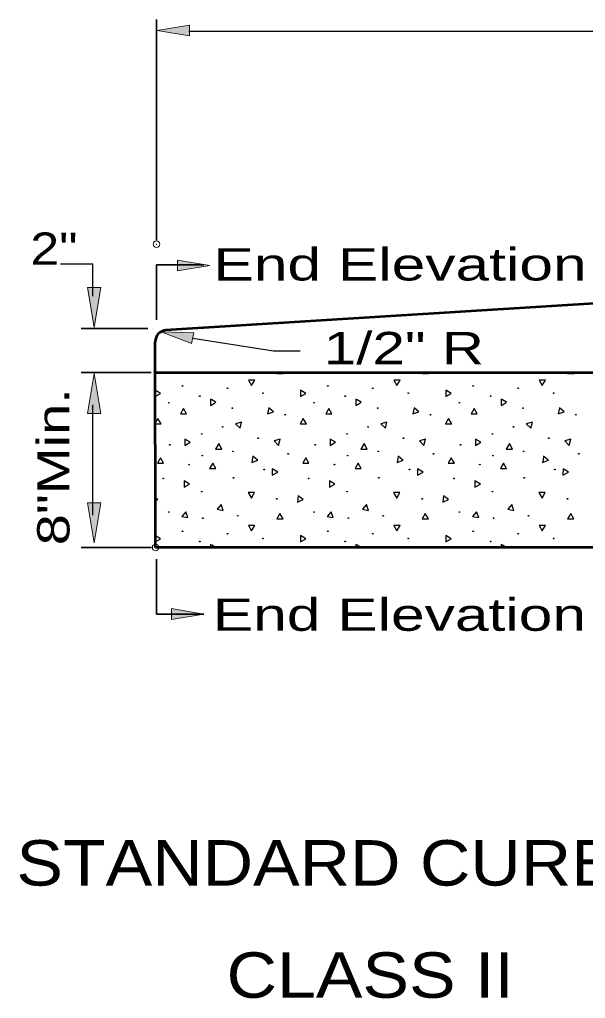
# Model space of a CAD drawing. Extents: x 75.6 to 110.9, y 28 to 50.
# Drawn here: x 82.636 to 85.264, y 34.838 to 39.383 of the extents above; entities that cross this region are included whole.
import ezdxf

# ---------------------------------------------------------------- set-up
doc = ezdxf.new("R2010")
doc.units = 0
doc.header["$LTSCALE"] = 0.06
doc.header["$PDMODE"] = 32
doc.header["$PDSIZE"] = 0.03
doc.layers.add('1', color=7, linetype='Continuous', lineweight=25)
doc.layers.add('3', color=7, linetype='Continuous', lineweight=13)

msp = doc.modelspace()

# ---------------------------------------------------------------- hatches: boundary and pattern name
at = {"layer": '3'}
for points in [[(83.42558, 39.3575), (83.42558, 39.3075), (83.27558, 39.3325), (83.27558, 39.3325)], [(83.36975, 38.216), (83.36975, 38.266), (83.51975, 38.241), (83.51975, 38.241)], [(82.9525, 38.1395), (83.014, 38.1395), (82.98317, 37.95492), (82.98317, 37.95492)], [(83.43533, 37.879), (83.44533, 37.928), (83.29333, 37.93342), (83.29333, 37.93342)], [(82.9525, 37.55467), (83.014, 37.55467), (82.98317, 37.73925), (82.98317, 37.73925)], [(82.9525, 37.1385), (83.014, 37.1385), (82.98317, 36.95392), (82.98317, 36.95392)], [(83.34183, 36.59792), (83.34183, 36.64792), (83.49183, 36.62292), (83.49183, 36.62292)]]:
    msp.add_hatch(color=256, dxfattribs=at).paths.add_polyline_path(points)

# ---------------------------------------------------------------- linework, layer by layer
at = {"layer": '1', "lineweight": 53}
for p, q in [((89.3085, 38.31592), (83.31608, 37.94033)), ((83.26817, 36.932), (83.26617, 37.8865)), ((83.26617, 37.74358), (90.5905, 37.74358)), ((90.61742, 36.932), (83.26817, 36.932))]:
    msp.add_line(p, q, dxfattribs=at)
at = {"layer": '1'}
for p, q in [((83.83375, 37.74358), (83.83117, 37.73917)), ((84.50875, 37.74358), (84.50617, 37.73917)), ((85.18375, 37.74358), (85.18117, 37.73917)), ((83.52325, 37.6205), (83.52317, 37.59142)), ((83.52317, 37.59142), (83.52908, 37.59475)), ((83.52908, 37.61717), (83.52325, 37.6205)), ((83.52908, 37.61717), (83.52325, 37.6205)), ((84.19825, 37.6205), (84.19817, 37.59142)), ((84.19817, 37.59142), (84.20408, 37.59475)), ((84.20408, 37.61717), (84.19825, 37.6205)), ((84.20408, 37.61717), (84.19825, 37.6205)), ((84.87325, 37.6205), (84.87317, 37.59142)), ((84.87317, 37.59142), (84.87908, 37.59475)), ((84.87908, 37.61717), (84.87325, 37.6205)), ((84.87908, 37.61717), (84.87325, 37.6205)), ((83.28475, 37.338), (83.27625, 37.32358)), ((83.27625, 37.32358), (83.3055, 37.32358)), ((83.3055, 37.32358), (83.29708, 37.338)), ((83.52908, 37.316), (83.51917, 37.29892)), ((83.53375, 37.32408), (83.52908, 37.316)), ((83.54825, 37.29892), (83.53375, 37.32408)), ((83.71725, 37.338), (83.71525, 37.32658)), ((83.71525, 37.32658), (83.7425, 37.33667)), ((83.7425, 37.33667), (83.74083, 37.338)), ((83.95975, 37.338), (83.95125, 37.32358)), ((83.95125, 37.32358), (83.9805, 37.32358)), ((83.9805, 37.32358), (83.97208, 37.338)), ((84.20408, 37.316), (84.19417, 37.29892)), ((84.20875, 37.32408), (84.20408, 37.316)), ((84.22325, 37.29892), (84.20875, 37.32408)), ((84.39225, 37.338), (84.39025, 37.32658)), ((84.39025, 37.32658), (84.4175, 37.33667)), ((84.4175, 37.33667), (84.41583, 37.338)), ((84.63475, 37.338), (84.62625, 37.32358)), ((84.62625, 37.32358), (84.6555, 37.32358)), ((84.6555, 37.32358), (84.64708, 37.338)), ((84.87908, 37.316), (84.86917, 37.29892)), ((84.88375, 37.32408), (84.87908, 37.316)), ((84.89825, 37.29892), (84.88375, 37.32408)), ((85.06725, 37.338), (85.06525, 37.32658)), ((85.06525, 37.32658), (85.0925, 37.33667)), ((85.0925, 37.33667), (85.09083, 37.338)), ((83.51917, 37.29892), (83.52908, 37.29892)), ((83.52908, 37.29892), (83.54825, 37.29892)), ((84.19417, 37.29892), (84.20408, 37.29892)), ((84.20408, 37.29892), (84.22325, 37.29892)), ((84.86917, 37.29892), (84.87908, 37.29892)), ((84.87908, 37.29892), (84.89825, 37.29892)), ((83.52325, 36.9455), (83.52325, 36.932)), ((83.52325, 36.9455), (83.52325, 36.932)), ((83.52908, 36.94217), (83.52325, 36.9455)), ((83.52908, 36.94217), (83.52325, 36.9455)), ((83.54658, 36.932), (83.52908, 36.94217)), ((84.19825, 36.9455), (84.19825, 36.932)), ((84.19825, 36.9455), (84.19825, 36.932)), ((84.20408, 36.94217), (84.19825, 36.9455)), ((84.20408, 36.94217), (84.19825, 36.9455)), ((84.22158, 36.932), (84.20408, 36.94217)), ((84.87325, 36.9455), (84.87325, 36.932)), ((84.87325, 36.9455), (84.87325, 36.932)), ((84.87908, 36.94217), (84.87325, 36.9455)), ((84.87908, 36.94217), (84.87325, 36.9455)), ((84.89658, 36.932), (84.87908, 36.94217))]:
    msp.add_line(p, q, dxfattribs=at)
for points in [[(83.83117, 37.73917), (83.86025, 37.73917), (83.85767, 37.74358)], [(84.50617, 37.73917), (84.53525, 37.73917), (84.53267, 37.74358)], [(85.18117, 37.73917), (85.21025, 37.73917), (85.20767, 37.74358)], [(83.26617, 37.63283), (83.29133, 37.64733), (83.26625, 37.66192), (83.26617, 37.64733)], [(83.52325, 37.6205), (83.52317, 37.59142), (83.52908, 37.59475)], [(83.52908, 37.59475), (83.54842, 37.60592), (83.52908, 37.61717)], [(84.19825, 37.6205), (84.19817, 37.59142), (84.20408, 37.59475)], [(84.20408, 37.59475), (84.22342, 37.60592), (84.20408, 37.61717)], [(84.87325, 37.6205), (84.87317, 37.59142), (84.87908, 37.59475)], [(84.87908, 37.59475), (84.89842, 37.60592), (84.87908, 37.61717)], [(83.26617, 37.50533), (83.29325, 37.50533), (83.27875, 37.5305), (83.26617, 37.50875)], [(83.29708, 37.338), (83.29092, 37.34867), (83.28475, 37.338)], [(83.74083, 37.338), (83.72033, 37.35517), (83.71725, 37.338)], [(83.74083, 37.338), (83.72033, 37.35517), (83.71725, 37.338)], [(83.97208, 37.338), (83.96592, 37.34867), (83.95975, 37.338)], [(84.41583, 37.338), (84.39533, 37.35517), (84.39225, 37.338)], [(84.41583, 37.338), (84.39533, 37.35517), (84.39225, 37.338)], [(84.64708, 37.338), (84.64092, 37.34867), (84.63475, 37.338)], [(85.09083, 37.338), (85.07033, 37.35517), (85.06725, 37.338)], [(85.09083, 37.338), (85.07033, 37.35517), (85.06725, 37.338)], [(83.26617, 37.14892), (83.27833, 37.15458), (83.26617, 37.16308)], [(83.26617, 36.95783), (83.29133, 36.97233), (83.26625, 36.98692), (83.26617, 36.97233)]]:
    msp.add_lwpolyline(points, dxfattribs=at)
for points in [[(83.71383, 37.68408), (83.7285, 37.70933), (83.69933, 37.70933)], [(84.38883, 37.68408), (84.4035, 37.70933), (84.37433, 37.70933)], [(85.06383, 37.68408), (85.0785, 37.70933), (85.04933, 37.70933)], [(83.94108, 37.63275), (83.96633, 37.64733), (83.94125, 37.66192)], [(84.61608, 37.63275), (84.64133, 37.64733), (84.61625, 37.66192)], [(83.383, 37.55258), (83.41208, 37.55258), (83.39758, 37.57767)], [(83.78825, 37.55192), (83.81558, 37.56192), (83.79333, 37.5805)], [(84.058, 37.55258), (84.08708, 37.55258), (84.07258, 37.57767)], [(84.46325, 37.55192), (84.49058, 37.56192), (84.46833, 37.5805)], [(84.733, 37.55258), (84.76208, 37.55258), (84.74758, 37.57767)], [(85.13825, 37.55192), (85.16558, 37.56192), (85.14333, 37.5805)], [(83.66025, 37.48592), (83.66775, 37.51417), (83.63975, 37.50658)], [(83.93917, 37.50533), (83.96825, 37.50533), (83.95375, 37.5305)], [(84.33525, 37.48592), (84.34275, 37.51417), (84.31475, 37.50658)], [(84.61417, 37.50533), (84.64325, 37.50533), (84.62875, 37.5305)], [(85.01025, 37.48592), (85.01775, 37.51417), (84.98975, 37.50658)], [(83.40367, 37.40592), (83.42892, 37.4205), (83.40383, 37.43508)], [(83.54675, 37.38892), (83.57592, 37.38892), (83.56142, 37.41417)], [(83.83867, 37.40592), (83.84617, 37.43408), (83.81808, 37.42658)], [(84.07867, 37.40592), (84.10392, 37.4205), (84.07883, 37.43508)], [(84.22175, 37.38892), (84.25092, 37.38892), (84.23642, 37.41417)], [(84.51367, 37.40592), (84.52117, 37.43408), (84.49308, 37.42658)], [(84.75367, 37.40592), (84.77892, 37.4205), (84.75383, 37.43508)], [(84.89675, 37.38892), (84.92592, 37.38892), (84.91142, 37.41417)], [(85.18867, 37.40592), (85.19617, 37.43408), (85.16808, 37.42658)], [(83.81, 37.2675), (83.83525, 37.28208), (83.81017, 37.29667)], [(84.485, 37.2675), (84.51025, 37.28208), (84.48517, 37.29667)], [(85.16, 37.2675), (85.18525, 37.28208), (85.16017, 37.29667)], [(83.401, 37.21175), (83.42625, 37.22642), (83.40117, 37.24092)], [(84.076, 37.21175), (84.10125, 37.22642), (84.07617, 37.24092)], [(84.751, 37.21175), (84.77625, 37.22642), (84.75117, 37.24092)], [(83.71275, 37.16117), (83.72733, 37.18642), (83.69825, 37.18642)], [(84.38775, 37.16117), (84.40233, 37.18642), (84.37325, 37.18642)], [(85.06275, 37.16117), (85.07733, 37.18642), (85.04825, 37.18642)], [(83.55333, 37.10925), (83.582, 37.10417), (83.57208, 37.1315)], [(83.92692, 37.14233), (83.95333, 37.15458), (83.9295, 37.17125)], [(84.22833, 37.10925), (84.257, 37.10417), (84.24708, 37.1315)], [(84.60192, 37.14233), (84.62833, 37.15458), (84.6045, 37.17125)], [(84.90333, 37.10925), (84.932, 37.10417), (84.92208, 37.1315)], [(83.38983, 37.07575), (83.4185, 37.07067), (83.4085, 37.09808)], [(83.83117, 37.06417), (83.86025, 37.06417), (83.84575, 37.08925)], [(84.06483, 37.07575), (84.0935, 37.07067), (84.0835, 37.09808)], [(84.50617, 37.06417), (84.53525, 37.06417), (84.52075, 37.08925)], [(84.73983, 37.07575), (84.7685, 37.07067), (84.7585, 37.09808)], [(85.18117, 37.06417), (85.21025, 37.06417), (85.19575, 37.08925)], [(83.71383, 37.00908), (83.7285, 37.03433), (83.69933, 37.03433)], [(84.38883, 37.00908), (84.4035, 37.03433), (84.37433, 37.03433)], [(85.06383, 37.00908), (85.0785, 37.03433), (85.04933, 37.03433)], [(83.94108, 36.95775), (83.96633, 36.97233), (83.94125, 36.98692)], [(84.61608, 36.95775), (84.64133, 36.97233), (84.61625, 36.98692)]]:
    msp.add_lwpolyline(points, close=True, dxfattribs=at)
for centre in [(83.39296, 37.68203), (84.06796, 37.68203), (84.74296, 37.68203), (83.47385, 37.63461), (83.60221, 37.67089), (83.76674, 37.64856), (84.14885, 37.63461), (84.27721, 37.67089), (84.44174, 37.64856), (84.82385, 37.63461), (84.95221, 37.67089), (85.11674, 37.64856), (83.32883, 37.60395), (84.00383, 37.60395), (84.67883, 37.60395), (83.62448, 37.57886), (83.86996, 37.54815), (84.29948, 37.57886), (84.54496, 37.54815), (84.97448, 37.57886), (85.21996, 37.54815), (83.57988, 37.49241), (84.25488, 37.49241), (84.92988, 37.49241), (83.48223, 37.45894), (84.15723, 37.45894), (84.83223, 37.45894), (83.3344, 37.40871), (83.74441, 37.43936), (84.0094, 37.40871), (84.41941, 37.43936), (84.6844, 37.40871), (85.09441, 37.43936), (83.48498, 37.35853), (83.6273, 37.37805), (83.88391, 37.36686), (84.15998, 37.35853), (84.3023, 37.37805), (84.55891, 37.36686), (84.83498, 37.35853), (84.9773, 37.37805), (85.23391, 37.36686), (83.42361, 37.31663), (84.09861, 37.31663), (84.77361, 37.31663), (83.77231, 37.29429), (84.44731, 37.29429), (85.12231, 37.29429), (83.30369, 37.2525), (83.63005, 37.25526), (83.97869, 37.2525), (84.30505, 37.25526), (84.65369, 37.2525), (84.98005, 37.25526), (83.48223, 37.19113), (84.15723, 37.19113), (84.83223, 37.19113), (83.83086, 37.15766), (84.50586, 37.15766), (85.18086, 37.15766), (83.32883, 37.09629), (84.00383, 37.09629), (84.67883, 37.09629), (83.4878, 37.06839), (83.64963, 37.07953), (84.1628, 37.06839), (84.32463, 37.07953), (84.8378, 37.06839), (84.99963, 37.07953), (83.39296, 37.00703), (83.60221, 36.99589), (84.06796, 37.00703), (84.27721, 36.99589), (84.74296, 37.00703), (84.95221, 36.99589), (83.47385, 36.95961), (83.76674, 36.97356), (84.14885, 36.95961), (84.44174, 36.97356), (84.82385, 36.95961), (85.11674, 36.97356)]:
    msp.add_circle(centre, 0.00162, dxfattribs=at)
at = {"layer": '1', "lineweight": 53}
msp.add_arc((83.32015, 37.88648), 0.054, 94.37495, 180, dxfattribs=at)
at = {"layer": '1'}
for centre in [(83.4878, 37.74339), (84.1628, 37.74339), (84.8378, 37.74339)]:
    msp.add_arc(centre, 0.00162, 173.26839, 6.73161, dxfattribs=at)
at = {"layer": '3', "lineweight": 35}
for p, q in [((83.27208, 38.35858), (83.27208, 39.38283)), ((83.23267, 37.94833), (82.92275, 37.94833)), ((83.24767, 37.74358), (82.92275, 37.74358)), ((83.24942, 36.932), (82.92275, 36.932)), ((83.27208, 36.877), (83.27208, 36.62292)), ((83.27208, 36.62292), (83.49183, 36.62292))]:
    msp.add_line(p, q, dxfattribs=at)
at = {"layer": '3', "lineweight": 25}
for p, q in [((83.42208, 39.32883), (89.60558, 39.32883)), ((82.82675, 38.24833), (82.97675, 38.24833)), ((82.97675, 38.09833), (82.97675, 38.24833)), ((82.97675, 37.082), (82.97675, 37.59358))]:
    msp.add_line(p, q, dxfattribs=at)
at = {"layer": '3'}
for p, q in [((82.97675, 37.94833), (82.97683, 37.94833)), ((83.25142, 37.94833), (83.2515, 37.94833)), ((83.24767, 37.74358), (82.92275, 37.74358)), ((82.97675, 37.74358), (82.97683, 37.74358)), ((83.26642, 37.74358), (83.2665, 37.74358)), ((83.26642, 37.74358), (83.2665, 37.74358))]:
    msp.add_line(p, q, dxfattribs=at)
for points in [[(83.42558, 39.3575), (83.42558, 39.3075), (83.27558, 39.3325), (83.27558, 39.3325)], [(83.36975, 38.216), (83.36975, 38.266), (83.51975, 38.241), (83.51975, 38.241)], [(82.9525, 38.1395), (83.014, 38.1395), (82.98317, 37.95492), (82.98317, 37.95492)], [(83.43533, 37.879), (83.44533, 37.928), (83.29333, 37.93342), (83.29333, 37.93342)], [(82.9525, 37.55467), (83.014, 37.55467), (82.98317, 37.73925), (82.98317, 37.73925)], [(82.9525, 37.1385), (83.014, 37.1385), (82.98317, 36.95392), (82.98317, 36.95392)], [(83.34183, 36.59792), (83.34183, 36.64792), (83.49183, 36.62292), (83.49183, 36.62292)]]:
    msp.add_lwpolyline(points, close=True, dxfattribs=at)
at = {"layer": '3', "lineweight": 35}
msp.add_lwpolyline([(83.27208, 37.9895), (83.27208, 38.24367), (83.49183, 38.24367)], dxfattribs=at)
at = {"layer": '3', "lineweight": 25}
msp.add_lwpolyline([(83.44033, 37.9035), (83.81642, 37.84517), (83.94008, 37.84517)], dxfattribs=at)
at = {"layer": '3'}
for p in [(83.27208, 38.33983), (83.26817, 36.932)]:
    msp.add_point(p, dxfattribs=at)

# ---------------------------------------------------------------- texts
for s, height, width, p in [('2"', 0.15, 1.2, (82.6865, 38.24425)), ('End Elevation', 0.15, 1.4, (83.537, 38.17142)), ('1/2" R', 0.15, 1.35, (84.0495, 37.78283)), ('End Elevation', 0.15, 1.4, (83.53408, 36.545)), ('STANDARD CURB TAPER', 0.2109, 1.15, (82.62167, 35.36225)), ('CLASS II', 0.2109, 1.15, (83.59775, 34.84133))]:
    msp.add_text(s, height=height, dxfattribs=dict(at, width=width)).set_placement(p)
at = {"layer": '3', "width": 1.3}
msp.add_text('8"Min.', height=0.15, rotation=90, dxfattribs=at).set_placement((82.86817, 36.94192))

doc.saveas('drawing.dxf')
